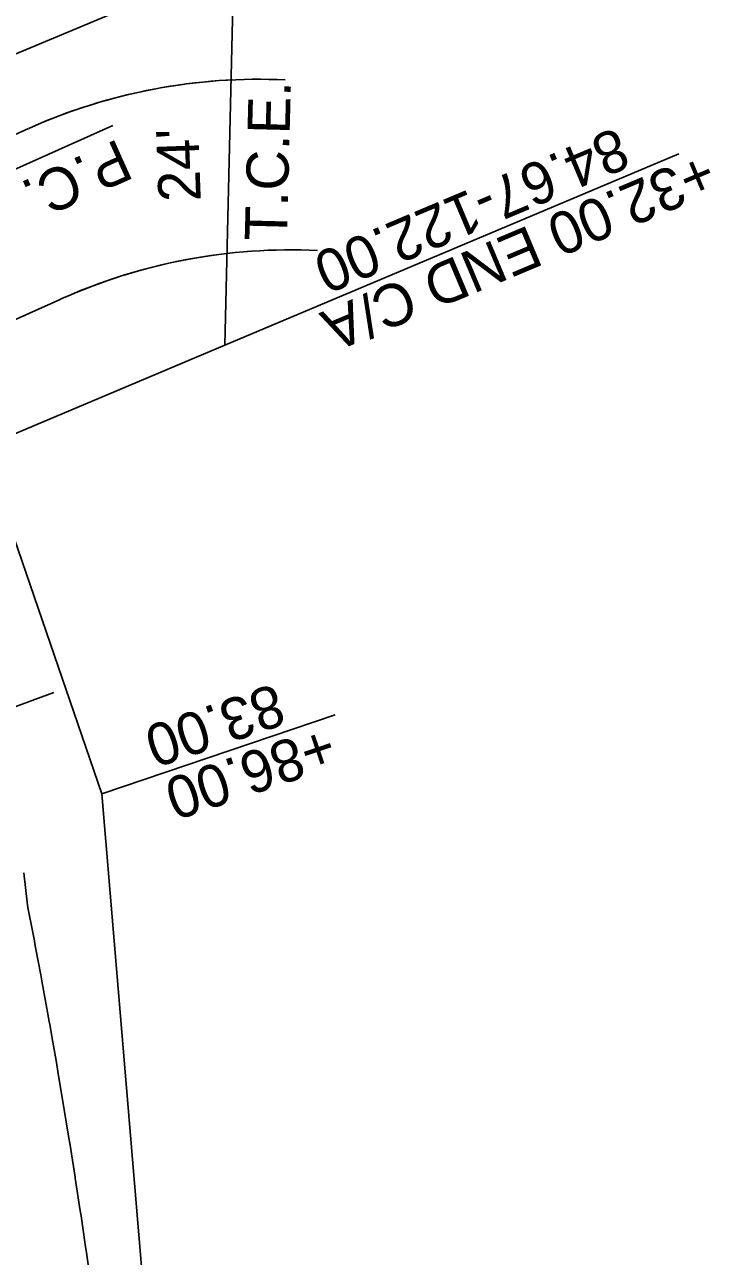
# Model space of a CAD drawing. Extents: x -70 to 701944, y -4 to 666871.
# Drawn here: x 668362.4 to 668459.8, y 655986.6 to 656161.6 of the extents above; entities that cross this region are included whole.
import ezdxf

# ---------------------------------------------------------------- set-up
doc = ezdxf.new("R2010")
doc.units = 0
for name, color, linetype in [('R_Detour', 7, 'Continuous'), ('R_Drive', 7, 'Continuous'), ('R_Horz Alg Annot', 7, 'Continuous'), ('R_Proposed Const Limits', 7, 'Continuous'), ('R_ROW', 7, 'Continuous'), ('R_ROW Annot', 7, 'Continuous'), ('R_Temp Easement', 7, 'Continuous'), ('R_Temp Easement Annot', 7, 'Continuous'), ('T_Indications', 7, 'Continuous')]:
    doc.layers.add(name, color=color, linetype=linetype)

msp = doc.modelspace()

# ---------------------------------------------------------------- linework, layer by layer
at = {"layer": 'R_Detour'}
msp.add_line((668366.51, 656066.66), (668287.45, 656037.95), dxfattribs=at)
at = {"layer": 'R_Drive'}
for p, q in [((668302.31, 656119.7), (668362.93, 656146.84)), ((668312.1, 656097.79), (668367.52, 656122.6))]:
    msp.add_line(p, q, dxfattribs=at)
for centre, start in [((668395.63, 656073.83), 87.2979), ((668395.63, 656073.83), 92.6754), ((668400.21, 656049.59), 87.2979), ((668400.21, 656049.59), 96.8037)]:
    msp.add_arc(centre, 80, start, 114.1233, dxfattribs=at)
at = {"layer": 'R_Horz Alg Annot'}
msp.add_lwpolyline([(668265.35, 656098.21), (668374.87, 656147.25)], dxfattribs=at)
at = {"layer": 'R_Proposed Const Limits'}
msp.add_lwpolyline([(668371.67, 655983.46), (668371.2, 655986.73), (668371.19, 655986.78), (668370.98, 655988.25), (668370.38, 655992.3), (668370.27, 655993.04), (668369.56, 655997.65), (668369.53, 655997.82), (668369.53, 655997.83), (668368.77, 656002.62), (668368.66, 656003.34), (668368, 656007.42), (668367.81, 656008.58), (668367.76, 656008.86), (668367.19, 656012.21), (668366.82, 656014.38), (668366.36, 656016.99), (668365.92, 656019.51), (668365.85, 656019.91), (668365.52, 656021.78), (668364.85, 656025.43), (668364.64, 656026.58), (668363.92, 656030.44), (668363.83, 656030.96), (668363.75, 656031.37), (668362.82, 656036.15), (668362.76, 656036.48), (668362.23, 656041.06)], dxfattribs=at)
at = {"layer": 'R_ROW'}
msp.add_lwpolyline([(668381.5, 655955.17), (668373.32, 656052.3), (668331.42, 656174.44), (668303.61, 656343.73), (668341.52, 656413.55)], dxfattribs=at)
at = {"layer": 'R_ROW Annot'}
for points in [[(668390.83, 656116.05), (668455.34, 656143.22)], [(668373.32, 656052.3), (668406.48, 656063.52)]]:
    msp.add_lwpolyline(points, dxfattribs=at)
at = {"layer": 'R_Temp Easement'}
for points in [[(668340.23, 656148.75), (668392.07, 656170.44)], [(668392.07, 656170.44), (668390.83, 656116.05), (668356.42, 656101.56)]]:
    msp.add_lwpolyline(points, dxfattribs=at)
at = {"layer": 'T_Indications'}
for radius in [679.12, 674.12, 671.12]:
    msp.add_arc((667691.7, 655821.57), radius, 357.29792, 24.12331, dxfattribs=at)

# ---------------------------------------------------------------- texts
at = {"layer": 'R_Drive'}
msp.add_text("24'", height=6, rotation=92.076, dxfattribs=at).set_placement((668387.4, 656136.53))
at = {"layer": 'R_Horz Alg Annot'}
msp.add_text('P.C. 128+64.27', height=6, rotation=204.1233, dxfattribs=at).set_placement((668375.69, 656145.43))
at = {"layer": 'R_ROW Annot'}
for s, rotation, p in [('+13.00', 200.2249, (668372.63, 656175.19)), ('84.67-122.00', 202.841, (668446.55, 656147.11)), ('+32.00 END C/A', 202.841, (668458.93, 656143.65)), ('83.00', 198.701, (668397.99, 656068.04)), ('+86.00', 198.701, (668405.29, 656062.07))]:
    msp.add_text(s, height=6, rotation=rotation, dxfattribs=at).set_placement(p)
at = {"layer": 'R_Temp Easement Annot'}
msp.add_text('T.C.E.', height=6, rotation=88.5327, dxfattribs=at).set_placement((668399.63, 656130.8))

doc.saveas('drawing.dxf')
